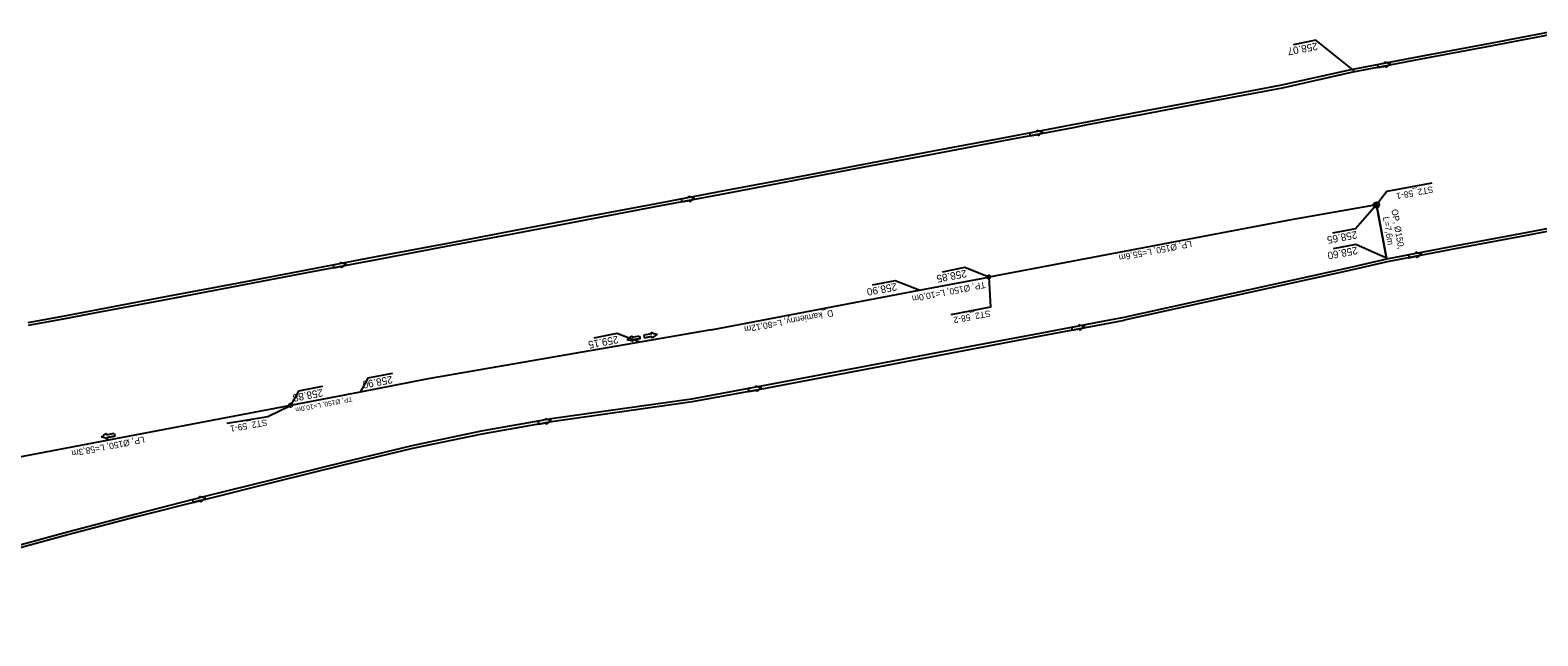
# Model space of a CAD drawing. Extents: x -1 to 65640748, y -22 to 5530284.
# Drawn here: x 6559962.5 to 6560175.2, y 5529123 to 5529208.4 of the extents above; entities that cross this region are included whole.
import ezdxf

# ---------------------------------------------------------------- set-up
doc = ezdxf.new("R2010")
doc.units = 0
for name, color, linetype in [('TOR_PROF-studnie i osadniki', 7, 'Continuous'), ('TOR_PS_ODW-drenaze', 7, 'Continuous'), ('TOR_PS_ODW-drenokolektory', 7, 'Continuous'), ('TOR_PS_ODW-kolektory', 7, 'Continuous'), ('TOR_PS_ODW-studnie PEHD', 7, 'Continuous'), ('TOR_PS_OPIS_O-opisy rurociagow', 7, 'Continuous'), ('TOR_PS_OPIS_O-opisy studni', 7, 'Continuous'), ('TOR_PS_OPIS_T-INFO', 7, 'Continuous'), ('TOR_PS_T-rowy otwarte umocnione', 7, 'Continuous')]:
    doc.layers.add(name, color=color, linetype=linetype)

msp = doc.modelspace()

# ---------------------------------------------------------------- linework, layer by layer
at = {"layer": 'TOR_PROF-studnie i osadniki'}
for radius in [0.25, 0.125]:
    msp.add_circle((6560097.75, 5529173.61), radius, dxfattribs=at)
at = {"layer": 'TOR_PS_ODW-drenaze'}
for p, q in [((6560087.92, 5529171.75), (6560097.75, 5529173.61)), ((6560058.59, 5529166.18), (6560087.92, 5529171.75))]:
    msp.add_line(p, q, dxfattribs=at)
for points in [[(6560058.59, 5529166.18), (6560018.69, 5529159.23), (6560009.1, 5529157.37)], [(6560009.1, 5529157.37), (6559999.28, 5529155.5)]]:
    msp.add_lwpolyline(points, dxfattribs=at)
at = {"layer": 'TOR_PS_ODW-drenokolektory'}
msp.add_line((6560152.43, 5529183.77), (6560153.85, 5529176.29), dxfattribs=at)
for points in [[(6560152.43, 5529183.77), (6560140.39, 5529181.69), (6560097.75, 5529173.61)], [(6559999.28, 5529155.5), (6559945.65, 5529145.28), (6559941.99, 5529144.54)]]:
    msp.add_lwpolyline(points, dxfattribs=at)
msp.add_circle((6560152.43, 5529183.77), 0.145, dxfattribs=at)
at = {"layer": 'TOR_PS_ODW-kolektory'}
msp.add_lwpolyline([(6560153.85, 5529176.29), (6560152.43, 5529183.77)], dxfattribs=at)
at = {"layer": 'TOR_PS_ODW-studnie PEHD'}
for centre, radius in [((6560152.43, 5529183.77), 0.4), ((6560097.75, 5529173.61), 0.25), ((6560097.75, 5529173.61), 0.112), ((6559999.28, 5529155.51), 0.25), ((6559999.28, 5529155.51), 0.112)]:
    msp.add_circle(centre, radius, dxfattribs=at)
at = {"layer": 'TOR_PS_OPIS_O-opisy rurociagow'}
for p, q in [((6560153.64, 5529203.75), (6560152.57, 5529203.55)), ((6560153.64, 5529203.75), (6560152.57, 5529203.55)), ((6560152.57, 5529203.55), (6560152.64, 5529203.15)), ((6560152.57, 5529203.55), (6560152.64, 5529203.15)), ((6560152.64, 5529203.15), (6560153.72, 5529203.36)), ((6560153.72, 5529203.36), (6560152.64, 5529203.15)), ((6560104.59, 5529194.12), (6560103.52, 5529193.92)), ((6560104.59, 5529194.12), (6560103.52, 5529193.92)), ((6560103.52, 5529193.92), (6560103.59, 5529193.53)), ((6560103.52, 5529193.92), (6560103.59, 5529193.53)), ((6560103.59, 5529193.53), (6560104.66, 5529193.73)), ((6560104.66, 5529193.73), (6560103.59, 5529193.53)), ((6560055.46, 5529184.81), (6560054.39, 5529184.61)), ((6560055.46, 5529184.81), (6560054.39, 5529184.61)), ((6560054.39, 5529184.61), (6560054.46, 5529184.21)), ((6560054.39, 5529184.61), (6560054.46, 5529184.21)), ((6560054.46, 5529184.21), (6560055.54, 5529184.42)), ((6560055.54, 5529184.42), (6560054.46, 5529184.21)), ((6560158.03, 5529176.92), (6560156.95, 5529176.72)), ((6560158.03, 5529176.92), (6560156.95, 5529176.72)), ((6560156.95, 5529176.72), (6560157.03, 5529176.33)), ((6560156.95, 5529176.72), (6560157.03, 5529176.33)), ((6560006.34, 5529175.5), (6560005.27, 5529175.29)), ((6560006.34, 5529175.5), (6560005.27, 5529175.29)), ((6560005.27, 5529175.29), (6560005.34, 5529174.9)), ((6560005.27, 5529175.29), (6560005.34, 5529174.9)), ((6560005.34, 5529174.9), (6560006.41, 5529175.1)), ((6560006.41, 5529175.1), (6560005.34, 5529174.9)), ((6560157.03, 5529176.33), (6560158.1, 5529176.53)), ((6560158.1, 5529176.53), (6560157.03, 5529176.33)), ((6560110.5, 5529166.7), (6560109.43, 5529166.5)), ((6560110.5, 5529166.7), (6560109.43, 5529166.5)), ((6560109.43, 5529166.5), (6560109.5, 5529166.11)), ((6560109.43, 5529166.5), (6560109.5, 5529166.11)), ((6560109.5, 5529166.11), (6560110.57, 5529166.31)), ((6560110.57, 5529166.31), (6560109.5, 5529166.11)), ((6560047.44, 5529165.12), (6560048.51, 5529165.33)), ((6560047.44, 5529165.12), (6560048.51, 5529165.33)), ((6560048.59, 5529164.94), (6560047.52, 5529164.73)), ((6560047.52, 5529164.73), (6560048.59, 5529164.94)), ((6560048.51, 5529165.33), (6560048.59, 5529164.94)), ((6560048.51, 5529165.33), (6560048.59, 5529164.94)), ((6560050.17, 5529165.6), (6560049.1, 5529165.41)), ((6560050.17, 5529165.6), (6560049.1, 5529165.41)), ((6560049.1, 5529165.41), (6560049.17, 5529165.02)), ((6560049.1, 5529165.41), (6560049.17, 5529165.02)), ((6560049.17, 5529165.02), (6560050.24, 5529165.21)), ((6560050.24, 5529165.21), (6560049.17, 5529165.02)), ((6560064.91, 5529158.06), (6560063.84, 5529157.87)), ((6560064.91, 5529158.06), (6560063.84, 5529157.87)), ((6560063.84, 5529157.87), (6560063.91, 5529157.47)), ((6560063.84, 5529157.87), (6560063.91, 5529157.47)), ((6560063.91, 5529157.47), (6560064.98, 5529157.67)), ((6560064.98, 5529157.67), (6560063.91, 5529157.47)), ((6560035.25, 5529153.45), (6560034.18, 5529153.26)), ((6560035.25, 5529153.45), (6560034.18, 5529153.26)), ((6560034.18, 5529153.26), (6560034.24, 5529152.87)), ((6560034.18, 5529153.26), (6560034.24, 5529152.87)), ((6559973.32, 5529151.37), (6559974.39, 5529151.59)), ((6559973.32, 5529151.37), (6559974.39, 5529151.59)), ((6559974.47, 5529151.19), (6559973.4, 5529150.98)), ((6559973.4, 5529150.98), (6559974.47, 5529151.19)), ((6559974.39, 5529151.59), (6559974.47, 5529151.19)), ((6559974.39, 5529151.59), (6559974.47, 5529151.19)), ((6560034.24, 5529152.87), (6560035.32, 5529153.06)), ((6560035.32, 5529153.06), (6560034.24, 5529152.87)), ((6559986.49, 5529142.47), (6559985.43, 5529142.21)), ((6559986.49, 5529142.47), (6559985.43, 5529142.21)), ((6559985.43, 5529142.21), (6559985.53, 5529141.82)), ((6559985.43, 5529142.21), (6559985.53, 5529141.82)), ((6559985.53, 5529141.82), (6559986.59, 5529142.08)), ((6559986.59, 5529142.08), (6559985.53, 5529141.82))]:
    msp.add_line(p, q, dxfattribs=at)
for points in [[(6560153.59, 5529203.97), (6560153.59, 5529203.97)], [(6560153.75, 5529203.14), (6560153.75, 5529203.14)], [(6560104.54, 5529194.34), (6560104.54, 5529194.34)], [(6560104.7, 5529193.51), (6560104.7, 5529193.51)], [(6560055.41, 5529185.03), (6560055.41, 5529185.03)], [(6560055.57, 5529184.19), (6560055.57, 5529184.19)], [(6560157.98, 5529177.14), (6560157.98, 5529177.14)], [(6560006.29, 5529175.72), (6560006.29, 5529175.72)], [(6560006.44, 5529174.88), (6560006.44, 5529174.88)], [(6560158.13, 5529176.31), (6560158.13, 5529176.31)], [(6560110.45, 5529166.92), (6560110.45, 5529166.92)], [(6560110.61, 5529166.09), (6560110.61, 5529166.09)], [(6560047.41, 5529165.34), (6560047.41, 5529165.34)], [(6560047.58, 5529164.51), (6560047.58, 5529164.51)], [(6560050.12, 5529165.82), (6560050.12, 5529165.82)], [(6560050.27, 5529164.99), (6560050.27, 5529164.99)], [(6560064.86, 5529158.28), (6560064.86, 5529158.28)], [(6560065.01, 5529157.45), (6560065.01, 5529157.45)], [(6560035.2, 5529153.67), (6560035.2, 5529153.67)], [(6559973.28, 5529151.59), (6559973.28, 5529151.59)], [(6560035.35, 5529152.84), (6560035.35, 5529152.84)], [(6559973.45, 5529150.76), (6559973.45, 5529150.76)], [(6559986.43, 5529142.69), (6559986.43, 5529142.69)], [(6559986.63, 5529141.86), (6559986.63, 5529141.86)]]:
    msp.add_lwpolyline(points, dxfattribs=at)
for centre, radius, start, end in [((6560155.51, 5529208.5), 4.92, 247.0269, 257.4087), ((6560154.05, 5529203.96), 0.458, 179.1415, 207.6027), ((6560155.51, 5529208.5), 4.92, 247.0269, 257.4087), ((6560154.05, 5529203.96), 0.458, 179.1415, 207.6027), ((6560154.17, 5529203.31), 0.458, 173.8708, 202.3321), ((6560154.17, 5529203.31), 0.458, 173.8708, 202.3321), ((6560157.19, 5529199.62), 4.92, 124.0648, 134.4466), ((6560157.19, 5529199.62), 4.92, 124.0648, 134.4466), ((6560106.46, 5529198.87), 4.92, 247.0242, 257.406), ((6560104.99, 5529194.33), 0.458, 179.1387, 207.6), ((6560106.46, 5529198.87), 4.92, 247.0242, 257.406), ((6560104.99, 5529194.33), 0.458, 179.1387, 207.6), ((6560105.12, 5529193.68), 0.458, 173.8681, 202.3293), ((6560105.12, 5529193.68), 0.458, 173.8681, 202.3293), ((6560108.14, 5529190), 4.92, 124.062, 134.4439), ((6560108.14, 5529190), 4.92, 124.062, 134.4439), ((6560057.33, 5529189.56), 4.92, 247.0242, 257.406), ((6560055.87, 5529185.02), 0.458, 179.1387, 207.6), ((6560057.33, 5529189.56), 4.92, 247.0242, 257.406), ((6560055.87, 5529185.02), 0.458, 179.1387, 207.6), ((6560055.99, 5529184.37), 0.458, 173.8681, 202.3293), ((6560055.99, 5529184.37), 0.458, 173.8681, 202.3293), ((6560059.01, 5529180.68), 4.92, 124.062, 134.4439), ((6560059.01, 5529180.68), 4.92, 124.062, 134.4439), ((6560159.9, 5529181.67), 4.92, 247.0207, 257.4025), ((6560158.43, 5529177.14), 0.458, 179.1352, 207.5965), ((6560159.9, 5529181.67), 4.92, 247.0207, 257.4025), ((6560158.43, 5529177.14), 0.458, 179.1352, 207.5965), ((6560161.58, 5529172.8), 4.92, 124.0586, 134.4404), ((6560161.58, 5529172.8), 4.92, 124.0586, 134.4404), ((6560008.21, 5529180.24), 4.92, 247.0242, 257.406), ((6560006.74, 5529175.71), 0.458, 179.1387, 207.6), ((6560008.21, 5529180.24), 4.92, 247.0242, 257.406), ((6560006.74, 5529175.71), 0.458, 179.1387, 207.6), ((6560006.87, 5529175.06), 0.458, 173.8681, 202.3293), ((6560006.87, 5529175.06), 0.458, 173.8681, 202.3293), ((6560009.89, 5529171.37), 4.92, 124.062, 134.4439), ((6560009.89, 5529171.37), 4.92, 124.062, 134.4439), ((6560158.56, 5529176.48), 0.458, 173.8646, 202.3258), ((6560158.56, 5529176.48), 0.458, 173.8646, 202.3258), ((6560112.37, 5529171.45), 4.92, 247.0243, 257.4061), ((6560110.9, 5529166.91), 0.458, 179.1389, 207.6001), ((6560112.37, 5529171.45), 4.92, 247.0243, 257.4061), ((6560110.9, 5529166.91), 0.458, 179.1389, 207.6001), ((6560111.03, 5529166.26), 0.458, 173.8682, 202.3295), ((6560111.03, 5529166.26), 0.458, 173.8682, 202.3295), ((6560114.05, 5529162.58), 4.92, 124.0622, 134.444), ((6560114.05, 5529162.58), 4.92, 124.0622, 134.444), ((6560043.93, 5529168.81), 4.92, 304.7037, 315.0855), ((6560043.93, 5529168.81), 4.92, 304.7037, 315.0855), ((6560045.71, 5529159.96), 4.92, 67.6658, 78.0476), ((6560045.71, 5529159.96), 4.92, 67.6658, 78.0476), ((6560046.99, 5529165.16), 0.458, 354.5097, 22.9709), ((6560046.99, 5529165.16), 0.458, 354.5097, 22.9709), ((6560047.12, 5529164.51), 0.458, 359.7803, 28.2416), ((6560047.12, 5529164.51), 0.458, 359.7803, 28.2416), ((6560052.09, 5529170.33), 4.92, 246.381, 256.7628), ((6560050.58, 5529165.81), 0.458, 178.4955, 206.9568), ((6560052.09, 5529170.33), 4.92, 246.381, 256.7628), ((6560050.58, 5529165.81), 0.458, 178.4955, 206.9568), ((6560050.7, 5529165.15), 0.458, 173.2249, 201.6861), ((6560050.7, 5529165.15), 0.458, 173.2249, 201.6861), ((6560053.68, 5529161.44), 4.92, 123.4189, 133.8007), ((6560053.68, 5529161.44), 4.92, 123.4189, 133.8007), ((6560066.8, 5529162.8), 4.92, 246.7163, 257.0981), ((6560065.32, 5529158.27), 0.458, 178.8309, 207.2921), ((6560066.8, 5529162.8), 4.92, 246.7163, 257.0981), ((6560065.32, 5529158.27), 0.458, 178.8309, 207.2921), ((6560065.44, 5529157.62), 0.458, 173.5602, 202.0214), ((6560065.44, 5529157.62), 0.458, 173.5602, 202.0214), ((6560068.44, 5529153.92), 4.92, 123.7542, 134.136), ((6560068.44, 5529153.92), 4.92, 123.7542, 134.136), ((6560037.19, 5529158.17), 4.92, 246.2112, 256.593), ((6560035.66, 5529153.66), 0.458, 178.3257, 206.787), ((6560037.19, 5529158.17), 4.92, 246.2112, 256.593), ((6560035.66, 5529153.66), 0.458, 178.3257, 206.787), ((6560038.74, 5529149.28), 4.92, 123.2491, 133.6309), ((6560038.74, 5529149.28), 4.92, 123.2491, 133.6309), ((6559969.8, 5529155.06), 4.92, 304.7037, 315.0855), ((6559969.8, 5529155.06), 4.92, 304.7037, 315.0855), ((6559972.86, 5529151.41), 0.458, 354.5097, 22.9709), ((6559972.86, 5529151.41), 0.458, 354.5097, 22.9709), ((6560035.77, 5529153), 0.458, 173.0551, 201.5163), ((6560035.77, 5529153), 0.458, 173.0551, 201.5163), ((6559971.58, 5529146.21), 4.92, 67.6658, 78.0476), ((6559971.58, 5529146.21), 4.92, 67.6658, 78.0476), ((6559972.99, 5529150.76), 0.458, 359.7803, 28.2416), ((6559972.99, 5529150.76), 0.458, 359.7803, 28.2416), ((6559988.09, 5529147.32), 4.92, 250.2584, 260.6402), ((6559986.88, 5529142.71), 0.458, 182.3729, 210.8342), ((6559988.09, 5529147.32), 4.92, 250.2584, 260.6402), ((6559986.88, 5529142.71), 0.458, 182.3729, 210.8342), ((6559987.04, 5529142.06), 0.458, 177.1023, 205.5635), ((6559987.04, 5529142.06), 0.458, 177.1023, 205.5635), ((6559990.27, 5529138.55), 4.92, 127.2963, 137.6781), ((6559990.27, 5529138.55), 4.92, 127.2963, 137.6781)]:
    msp.add_arc(centre, radius, start, end, dxfattribs=at)
at = {"layer": 'TOR_PS_OPIS_T-INFO'}
for points in [[(6560149.3, 5529202.71), (6560143.91, 5529206.99), (6560140.68, 5529206.37)], [(6560160.26, 5529186.83), (6560153.91, 5529185.68), (6560152.43, 5529183.77)], [(6560152.43, 5529183.77), (6560149.48, 5529180.41), (6560146.25, 5529179.78)], [(6560153.85, 5529176.29), (6560149.55, 5529178.2), (6560146.32, 5529177.57)], [(6560097.75, 5529173.61), (6560094.39, 5529174.94), (6560091.16, 5529174.31)], [(6560087.92, 5529171.75), (6560084.57, 5529173.08), (6560081.33, 5529172.45)], [(6560097.75, 5529173.61), (6560098, 5529169.37), (6560092.4, 5529168.29)], [(6560048.53, 5529164.42), (6560045.27, 5529165.63), (6560042.03, 5529165)], [(6560013.58, 5529160.01), (6560013.58, 5529160.01), (6560010.19, 5529159.36), (6560009.1, 5529157.37)], [(6560003.75, 5529158.15), (6560003.75, 5529158.15), (6560000.37, 5529157.5), (6559999.28, 5529155.51)], [(6559990.32, 5529152.98), (6559990.32, 5529152.98), (6559996.07, 5529153.95), (6559999.28, 5529155.51)]]:
    msp.add_lwpolyline(points, dxfattribs=at)
at = {"layer": 'TOR_PS_T-rowy otwarte umocnione'}
for points in [[(6560178.29, 5529208.42), (6560168.46, 5529206.56), (6560158.64, 5529204.7), (6560148.81, 5529202.84), (6560139.05, 5529200.66), (6560129.22, 5529198.79), (6560119.4, 5529196.93), (6560111.58, 5529195.45), (6560111.58, 5529195.45), (6560111.58, 5529195.45), (6560109.57, 5529195.07), (6560099.75, 5529193.21), (6560089.92, 5529191.34), (6560080.1, 5529189.48), (6560070.27, 5529187.62), (6560060.45, 5529185.76), (6560050.62, 5529183.89), (6560040.8, 5529182.03), (6560030.97, 5529180.17), (6560021.15, 5529178.31), (6560011.32, 5529176.44), (6560001.5, 5529174.58), (6559991.67, 5529172.72), (6559981.85, 5529170.86), (6559972.02, 5529168.99), (6559967.11, 5529168.06), (6559962.2, 5529167.14)], [(6560178.36, 5529208.03), (6560168.54, 5529206.17), (6560158.71, 5529204.31), (6560148.89, 5529202.44), (6560139.12, 5529200.26), (6560129.3, 5529198.4), (6560119.47, 5529196.54), (6560111.65, 5529195.05), (6560111.65, 5529195.05), (6560111.65, 5529195.05), (6560109.65, 5529194.67), (6560099.82, 5529192.81), (6560090, 5529190.95), (6560080.17, 5529189.09), (6560070.35, 5529187.22), (6560060.52, 5529185.36), (6560050.7, 5529183.5), (6560040.87, 5529181.64), (6560031.05, 5529179.77), (6560021.22, 5529177.91), (6560011.4, 5529176.05), (6560001.57, 5529174.19), (6559991.75, 5529172.32), (6559981.92, 5529170.46), (6559972.1, 5529168.6), (6559967.18, 5529167.67), (6559962.27, 5529166.75)], [(6560183.35, 5529181.72), (6560173.52, 5529179.86), (6560163.7, 5529178), (6560153.87, 5529176.14), (6560149, 5529175), (6560116.8, 5529167.9), (6560116.8, 5529167.9), (6560114.8, 5529167.52), (6560104.97, 5529165.65), (6560095.15, 5529163.79), (6560065.67, 5529158.2)], [(6560183.42, 5529181.33), (6560173.6, 5529179.47), (6560163.77, 5529177.61), (6560153.95, 5529175.74), (6560149.07, 5529174.61), (6560116.87, 5529167.51), (6560116.87, 5529167.5), (6560114.87, 5529167.12), (6560105.04, 5529165.26), (6560095.22, 5529163.4), (6560065.74, 5529157.81)], [(6560065.67, 5529158.2), (6560055.84, 5529156.39), (6560036.01, 5529153.59)], [(6560065.74, 5529157.81), (6560055.91, 5529156), (6560036.09, 5529153.19)], [(6560036.01, 5529153.59), (6560026.16, 5529151.86), (6560016.37, 5529149.81), (6560006.64, 5529147.46), (6559996.91, 5529145.06), (6559987.19, 5529142.65), (6559977.48, 5529140.18), (6559972.63, 5529138.92), (6559967.79, 5529137.64), (6559958.11, 5529135.01), (6559948.45, 5529132.25), (6559938.83, 5529129.35), (6559929.23, 5529126.29), (6559920.4, 5529123.33)], [(6560036.09, 5529153.19), (6560026.23, 5529151.47), (6560016.45, 5529149.42), (6560006.71, 5529147.07), (6559996.99, 5529144.67), (6559987.27, 5529142.25), (6559977.56, 5529139.79), (6559972.71, 5529138.53), (6559967.86, 5529137.25), (6559958.18, 5529134.62), (6559948.53, 5529131.86), (6559938.9, 5529128.95), (6559929.3, 5529125.89), (6559920.69, 5529123.01)]]:
    msp.add_lwpolyline(points, dxfattribs=at)

# ---------------------------------------------------------------- texts
at = {"layer": 'TOR_PS_OPIS_O-opisy rurociagow'}
for s, height, rotation, p in [('OP, Ø150, ', 0.9, 279.814, (6560154.54, 5529183.11)), ('L=7,6m', 0.9, 279.814, (6560153.35, 5529182.05)), ('LP, Ø150, L=55,6m', 0.9, 191.0542, (6560126.3, 5529178.75)), ('TP, Ø150, L=10,0m', 0.9, 191.0542, (6560097.2, 5529172.97)), ('D_kamienny, L=80,12m', 0.9, 190.5985, (6560075.73, 5529168.98)), ('TP, Ø150, L=10,0m', 0.675, 191.0542, (6560007.91, 5529156.75)), ('LP, Ø150, L=58,3m', 0.9, 191.0542, (6559978.59, 5529151.14))]:
    msp.add_text(s, height=height, rotation=rotation, dxfattribs=at).set_placement(p)
at = {"layer": 'TOR_PS_OPIS_O-opisy studni'}
for s, rotation, p in [('ST2_58-1', 190.8653, (6560160.35, 5529186.42)), ('ST2_58-2', 190.6779, (6560097.91, 5529168.93)), ('ST2_59-1', 190.146, (6559995.89, 5529153.56))]:
    msp.add_text(s, height=0.9, rotation=rotation, dxfattribs=at).set_placement(p)
at = {"layer": 'TOR_PS_OPIS_T-INFO'}
for s, p in [('258.07', (6560144.04, 5529206.69)), ('258.65', (6560149.61, 5529180.11)), ('258.60', (6560149.68, 5529177.9)), ('258.85', (6560094.53, 5529174.64)), ('258.90', (6560084.7, 5529172.78)), ('259.15', (6560045.4, 5529165.33)), ('258.90', (6560013.56, 5529159.69)), ('258.88', (6560003.74, 5529157.83))]:
    msp.add_text(s, height=1.05, rotation=190.7159, dxfattribs=at).set_placement(p)

doc.saveas('drawing.dxf')
